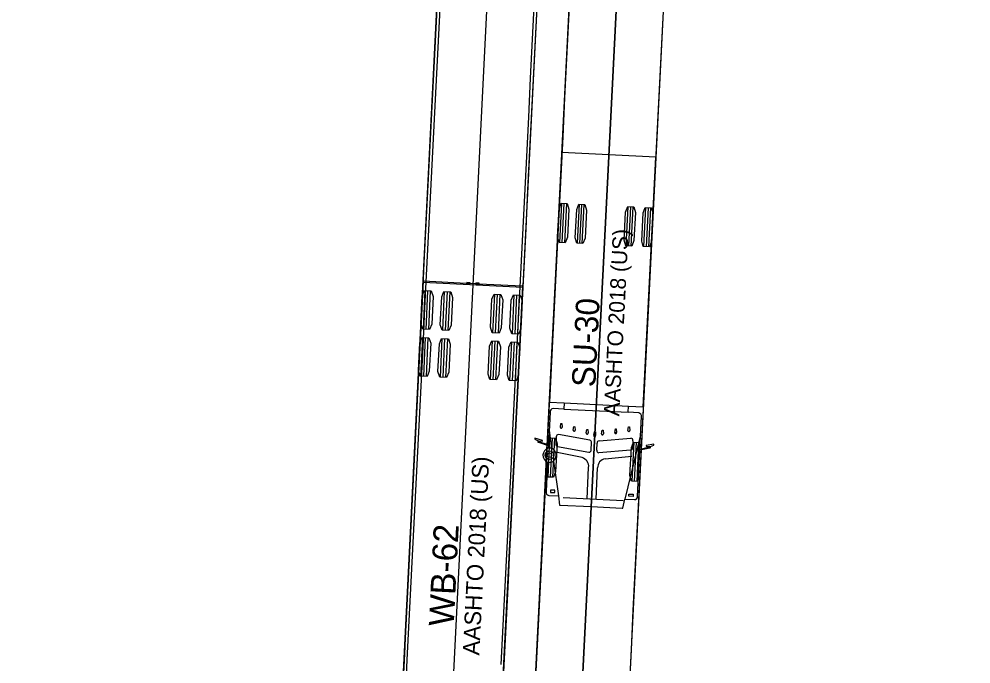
# Model space of a CAD drawing. Extents: x 260275 to 261282, y 610916 to 614143.
# Drawn here: x 260986.2 to 261067.3, y 611872.3 to 611927.2 of the extents above; entities that cross this region are included whole.
import ezdxf

# ---------------------------------------------------------------- set-up
doc = ezdxf.new("R2010")
doc.units = 0
doc.layers.add('GE_X_Alignment', color=7, linetype='Continuous')
doc.layers.add('UT_X_Water_Cells', color=7, linetype='Continuous')

msp = doc.modelspace()

# ---------------------------------------------------------------- linework, layer by layer
at = {"layer": 'GE_X_Alignment'}
msp.add_line((260986.249, 610915.954), (261148.276, 614142.838), dxfattribs=at)
at = {"layer": 'UT_X_Water_Cells'}
for p, q in [((261044.031, 612066.726), (261023.69, 611661.632)), ((261031.95, 612045.486), (261010.925, 611626.741)), ((261032.272, 611908.143), (261032.439, 611911.472)), ((261032.48, 611908.133), (261032.647, 611911.462)), ((261032.688, 611908.122), (261032.855, 611911.452)), ((261033.77, 611908.068), (261033.937, 611911.397)), ((261033.978, 611908.058), (261034.145, 611911.387)), ((261034.186, 611908.047), (261034.353, 611911.376)), ((261037.931, 611907.859), (261038.098, 611911.188)), ((261038.139, 611907.849), (261038.306, 611911.178)), ((261038.347, 611907.838), (261038.515, 611911.167)), ((261039.429, 611907.784), (261039.597, 611911.113)), ((261039.637, 611907.773), (261039.805, 611911.103)), ((261039.846, 611907.763), (261040.013, 611911.092)), ((261020.629, 611904.765), (261029.119, 611904.339)), ((261020.657, 611900.75), (261020.823, 611904.046)), ((261020.886, 611900.739), (261021.052, 611904.035)), ((261021.115, 611900.727), (261021.28, 611904.023)), ((261024.347, 611904.649), (261024.612, 611904.636)), ((261025.137, 611904.61), (261024.614, 611904.636)), ((261024.878, 611904.623), (261024.874, 611904.552)), ((261025.143, 611904.61), (261025.408, 611904.596)), ((261022.305, 611900.667), (261022.471, 611903.963)), ((261022.534, 611900.656), (261022.699, 611903.952)), ((261022.763, 611900.644), (261022.928, 611903.94)), ((261026.583, 611900.453), (261026.749, 611903.749)), ((261026.812, 611900.441), (261026.977, 611903.737)), ((261027.041, 611900.43), (261027.206, 611903.726)), ((261028.231, 611900.37), (261028.396, 611903.666)), ((261028.46, 611900.358), (261028.625, 611903.654)), ((261028.689, 611900.347), (261028.854, 611903.643)), ((261020.457, 611896.755), (261020.622, 611900.051)), ((261020.685, 611896.744), (261020.851, 611900.04)), ((261020.914, 611896.732), (261021.08, 611900.028)), ((261022.105, 611896.672), (261022.27, 611899.968)), ((261022.333, 611896.661), (261022.499, 611899.957)), ((261022.562, 611896.65), (261022.728, 611899.945)), ((261026.382, 611896.458), (261026.548, 611899.754)), ((261026.611, 611896.446), (261026.777, 611899.742)), ((261026.84, 611896.435), (261027.006, 611899.731)), ((261028.03, 611896.375), (261028.196, 611899.671)), ((261028.259, 611896.363), (261028.425, 611899.659)), ((261028.488, 611896.352), (261028.654, 611899.648)), ((261032.633, 611894.488), (261038.118, 611894.213)), ((261032.606, 611893.957), (261038.091, 611893.682)), ((261032.316, 611892.43), (261032.367, 611892.728)), ((261032.367, 611892.728), (261032.449, 611892.724)), ((261032.449, 611892.724), (261032.47, 611892.422)), ((261031.36, 611892.142), (261031.576, 611890.608)), ((261033.421, 611892.164), (261033.472, 611892.462)), ((261033.472, 611892.462), (261033.554, 611892.457)), ((261033.554, 611892.457), (261033.575, 611892.156)), ((261034.527, 611891.926), (261034.578, 611892.223)), ((261034.578, 611892.223), (261034.661, 611892.219)), ((261034.661, 611892.219), (261034.682, 611891.918)), ((261035.166, 611891.725), (261035.217, 611892.023)), ((261035.217, 611892.023), (261035.3, 611892.019)), ((261035.3, 611892.019), (261035.321, 611891.718)), ((261035.822, 611891.861), (261035.873, 611892.158)), ((261035.873, 611892.158), (261035.956, 611892.154)), ((261035.956, 611892.154), (261035.977, 611891.853)), ((261036.947, 611891.973), (261036.998, 611892.285)), ((261036.998, 611892.285), (261037.081, 611892.28)), ((261037.081, 611892.28), (261037.102, 611891.965)), ((261038.074, 611892.141), (261038.125, 611892.439)), ((261038.125, 611892.439), (261038.207, 611892.434)), ((261038.207, 611892.434), (261038.228, 611892.133)), ((261031.269, 611888.168), (261031.436, 611891.498)), ((261031.477, 611888.158), (261031.644, 611891.487)), ((261031.685, 611888.148), (261031.852, 611891.477)), ((261031.968, 611891.592), (261031.937, 611890.976)), ((261034.832, 611891.298), (261032.159, 611891.784)), ((261034.943, 611890.473), (261034.974, 611891.089)), ((261035.418, 611890.449), (261035.449, 611891.065)), ((261035.61, 611891.259), (261038.319, 611891.475)), ((261039.15, 611891.751), (261037.809, 611886.283)), ((261038.426, 611887.809), (261038.594, 611891.138)), ((261038.49, 611891.264), (261038.459, 611890.648)), ((261038.634, 611887.799), (261038.802, 611891.128)), ((261038.843, 611887.788), (261039.01, 611891.117)), ((261034.166, 611889.822), (261031.91, 611890.283)), ((261032.078, 611890.766), (261034.751, 611890.28)), ((261038.298, 611890.454), (261035.589, 611890.238)), ((261031.224, 611889.442), (261031.098, 611886.923)), ((261031.728, 611889.533), (261032.146, 611886.567)), ((261036.126, 611889.724), (261038.404, 611889.955)), ((261034.589, 611886.322), (261034.723, 611888.986)), ((261035.354, 611886.283), (261035.488, 611888.948)), ((261031.48, 611887.057), (261031.471, 611886.863)), ((261031.859, 611887.038), (261031.48, 611887.057)), ((261031.849, 611886.844), (261031.859, 611887.038)), ((261031.471, 611886.863), (261031.849, 611886.844)), ((261032.555, 611886.424), (261037.653, 611886.168)), ((261038.133, 611886.529), (261038.142, 611886.723)), ((261038.511, 611886.51), (261038.133, 611886.529)), ((261038.142, 611886.723), (261038.521, 611886.704)), ((261038.521, 611886.704), (261038.511, 611886.51))]:
    msp.add_line(p, q, dxfattribs=at)
for points in [[(261009.34, 611680.102), (261030.965, 612110.617), (261039.455, 612110.191), (261039.447, 612110.045), (261039.447, 612110.045)], [(261039.447, 612110.045), (261018.12, 611685.301)], [(261020.965, 611687.133), (261041.34, 612092.893), (261049.33, 612092.492), (261049.322, 612092.345), (261049.322, 612092.345)], [(261049.322, 612092.345), (261028.546, 611678.469)], [(261033.183, 611930.456), (261033.016, 611927.127), (261032.849, 611923.799), (261032.682, 611920.47), (261032.515, 611917.141), (261032.348, 611913.813), (261032.181, 611910.484), (261032.014, 611907.155), (261031.846, 611903.827), (261031.679, 611900.498), (261031.512, 611897.17), (261031.345, 611893.841), (261031.178, 611890.512), (261031.011, 611887.184), (261030.844, 611883.855), (261030.676, 611880.526), (261030.509, 611877.198), (261030.342, 611873.869), (261030.175, 611870.541)], [(261033.183, 611930.453), (261033.016, 611927.124), (261032.849, 611923.795), (261032.682, 611920.467), (261032.515, 611917.138), (261032.348, 611913.81), (261032.18, 611910.481), (261032.013, 611907.152), (261031.846, 611903.824), (261031.679, 611900.495), (261031.512, 611897.166), (261031.345, 611893.838), (261031.178, 611890.509), (261031.011, 611887.181), (261030.843, 611883.852), (261030.676, 611880.523), (261030.509, 611877.195), (261030.342, 611873.866), (261030.175, 611870.538)], [(261041.173, 611930.055), (261041.006, 611926.726), (261040.839, 611923.397), (261040.672, 611920.069), (261040.505, 611916.74), (261040.338, 611913.412), (261040.171, 611910.083), (261040.003, 611906.754), (261039.836, 611903.426), (261039.669, 611900.097), (261039.502, 611896.768), (261039.335, 611893.44), (261039.168, 611890.111), (261039.001, 611886.783), (261038.833, 611883.454), (261038.666, 611880.125), (261038.499, 611876.797), (261038.332, 611873.468), (261038.165, 611870.139)], [(261041.173, 611930.051), (261041.006, 611926.723), (261040.839, 611923.394), (261040.672, 611920.066), (261040.505, 611916.737), (261040.338, 611913.408), (261040.17, 611910.08), (261040.003, 611906.751), (261039.836, 611903.423), (261039.669, 611900.094), (261039.502, 611896.765), (261039.335, 611893.437), (261039.168, 611890.108), (261039, 611886.779), (261038.833, 611883.451), (261038.666, 611880.122), (261038.499, 611876.794), (261038.332, 611873.465), (261038.165, 611870.136)], [(261021.882, 611929.704), (261021.714, 611926.376), (261021.547, 611923.047), (261021.38, 611919.718), (261021.213, 611916.39), (261021.046, 611913.061), (261020.879, 611909.732), (261020.712, 611906.404), (261020.544, 611903.075), (261020.377, 611899.746), (261020.21, 611896.418), (261020.043, 611893.089), (261019.876, 611889.76), (261019.709, 611886.432), (261019.542, 611883.103), (261019.374, 611879.774), (261019.207, 611876.446), (261019.04, 611873.117), (261018.873, 611869.789)], [(261022.106, 611929.184), (261021.939, 611925.855), (261021.771, 611922.526), (261021.604, 611919.198), (261021.437, 611915.869), (261021.27, 611912.54), (261021.103, 611909.212), (261020.936, 611905.883), (261020.769, 611902.554), (261020.601, 611899.226), (261020.434, 611895.897), (261020.267, 611892.568), (261020.1, 611889.24), (261019.933, 611885.911), (261019.766, 611882.582), (261019.599, 611879.254), (261019.432, 611875.925), (261019.264, 611872.597), (261019.097, 611869.268)], [(261030.371, 611929.278), (261030.204, 611925.949), (261030.037, 611922.621), (261029.869, 611919.292), (261029.702, 611915.963), (261029.535, 611912.635), (261029.368, 611909.306), (261029.201, 611905.977), (261029.034, 611902.649), (261028.867, 611899.32), (261028.699, 611895.991), (261028.532, 611892.663), (261028.365, 611889.334), (261028.198, 611886.006), (261028.031, 611882.677), (261027.864, 611879.348), (261027.697, 611876.02), (261027.53, 611872.691), (261027.362, 611869.362)], [(261030.096, 611928.782), (261029.929, 611925.454), (261029.761, 611922.125), (261029.594, 611918.796), (261029.427, 611915.468), (261029.26, 611912.139), (261029.093, 611908.81), (261028.926, 611905.482), (261028.759, 611902.153), (261028.591, 611898.825), (261028.424, 611895.496), (261028.257, 611892.167), (261028.09, 611888.839), (261027.923, 611885.51), (261027.756, 611882.181), (261027.589, 611878.853), (261027.421, 611875.524), (261027.254, 611872.195)], [(261038.99, 611893.637), (261038.095, 611893.682), (261038.092, 611893.686), (261038.118, 611894.212), (261038.129, 611894.212), (261039.371, 611894.15), (261040.438, 611915.41), (261036.443, 611915.61), (261032.448, 611915.811), (261031.381, 611894.551), (261032.622, 611894.489), (261032.633, 611894.487), (261032.607, 611893.961), (261032.603, 611893.957), (261031.708, 611894.002)], [(261020.655, 611904.835), (261020.633, 611904.836), (261018.229, 611856.967), (261022.474, 611856.754), (261026.719, 611856.541), (261029.122, 611904.41), (261029.1, 611904.411)], [(261024.618, 611904.706), (261024.352, 611904.72), (261024.35, 611904.719), (261024.347, 611904.65), (261024.311, 611904.651), (261020.68, 611904.834), (261020.679, 611904.834)], [(261029.076, 611904.412), (261029.075, 611904.412), (261025.444, 611904.594), (261025.408, 611904.596), (261025.412, 611904.666), (261025.41, 611904.667), (261025.144, 611904.68)], [(261031.438, 611893.7), (261031.299, 611890.929), (261031.294, 611890.918), (261030.488, 611891.178), (261030.488, 611891.178)], [(261039.921, 611890.704), (261039.92, 611890.704), (261039.093, 611890.526), (261039.089, 611890.538), (261039.228, 611893.309)], [(261030.478, 611891.199), (261030.48, 611891.243), (261030.48, 611891.243), (261030.797, 611891.236), (261030.8, 611891.236), (261030.803, 611891.292), (261030.8, 611891.293), (261030.152, 611891.465), (261030.149, 611891.465), (261030.146, 611891.4), (261030.434, 611891.254), (261030.434, 611891.254), (261030.432, 611891.206)], [(261030.469, 611891.132), (261030.47, 611891.131), (261031.289, 611890.864), (261031.295, 611890.851), (261031.284, 611890.624)], [(261038.888, 611886.532), (261039.085, 611890.46), (261039.092, 611890.472), (261039.934, 611890.656), (261039.935, 611890.656)], [(261039.979, 611890.727), (261039.982, 611890.774), (261039.983, 611890.775), (261040.284, 611890.891), (261040.287, 611890.956), (261040.284, 611890.956), (261039.622, 611890.85), (261039.619, 611890.849), (261039.616, 611890.793), (261039.619, 611890.793), (261039.935, 611890.769), (261039.936, 611890.768), (261039.933, 611890.724)], [(261031.336, 611886.608), (261032.142, 611886.567), (261032.147, 611886.563), (261032.256, 611885.785), (261032.298, 611885.781), (261034.939, 611885.648), (261037.579, 611885.515), (261037.621, 611885.515), (261037.808, 611886.278), (261037.813, 611886.283), (261038.62, 611886.242)]]:
    msp.add_lwpolyline(points, dxfattribs=at)
for points in [[(261032.739, 611908.12), (261032.22, 611908.146), (261032.087, 611908.62), (261032.207, 611911.017), (261032.387, 611911.475), (261032.907, 611911.449), (261033.04, 611910.975), (261032.919, 611908.578)], [(261034.238, 611908.045), (261033.718, 611908.071), (261033.585, 611908.545), (261033.706, 611910.942), (261033.885, 611911.4), (261034.405, 611911.374), (261034.538, 611910.9), (261034.417, 611908.503)], [(261038.399, 611907.836), (261037.88, 611907.862), (261037.747, 611908.336), (261037.867, 611910.733), (261038.047, 611911.191), (261038.566, 611911.165), (261038.699, 611910.691), (261038.579, 611908.294)], [(261039.897, 611907.76), (261039.378, 611907.787), (261039.245, 611908.26), (261039.365, 611910.657), (261039.545, 611911.116), (261040.064, 611911.09), (261040.197, 611910.616), (261040.077, 611908.219)], [(261021.172, 611900.724), (261020.6, 611900.753), (261020.451, 611901.223), (261020.571, 611903.596), (261020.766, 611904.049), (261021.337, 611904.02), (261021.486, 611903.55), (261021.367, 611901.177)], [(261022.82, 611900.642), (261022.248, 611900.67), (261022.099, 611901.14), (261022.219, 611903.513), (261022.414, 611903.966), (261022.985, 611903.937), (261023.134, 611903.467), (261023.015, 611901.094)], [(261027.098, 611900.427), (261026.526, 611900.456), (261026.377, 611900.926), (261026.496, 611903.299), (261026.692, 611903.751), (261027.263, 611903.723), (261027.412, 611903.253), (261027.293, 611900.88)], [(261028.745, 611900.344), (261028.174, 611900.373), (261028.025, 611900.843), (261028.144, 611903.216), (261028.34, 611903.669), (261028.911, 611903.64), (261029.06, 611903.17), (261028.941, 611900.797)], [(261020.971, 611896.729), (261020.4, 611896.758), (261020.251, 611897.228), (261020.37, 611899.601), (261020.565, 611900.054), (261021.137, 611900.025), (261021.286, 611899.555), (261021.166, 611897.182)], [(261022.619, 611896.647), (261022.048, 611896.675), (261021.899, 611897.145), (261022.018, 611899.518), (261022.213, 611899.971), (261022.785, 611899.943), (261022.933, 611899.472), (261022.814, 611897.099)], [(261026.897, 611896.432), (261026.326, 611896.461), (261026.177, 611896.931), (261026.296, 611899.304), (261026.491, 611899.756), (261027.062, 611899.728), (261027.211, 611899.258), (261027.092, 611896.885)], [(261028.545, 611896.349), (261027.974, 611896.378), (261027.825, 611896.848), (261027.944, 611899.221), (261028.139, 611899.674), (261028.71, 611899.645), (261028.859, 611899.175), (261028.74, 611896.802)], [(261031.736, 611888.145), (261031.217, 611888.171), (261031.084, 611888.645), (261031.204, 611891.042), (261031.384, 611891.5), (261031.904, 611891.474), (261032.037, 611891), (261031.916, 611888.603)], [(261038.894, 611887.786), (261038.375, 611887.812), (261038.242, 611888.286), (261038.362, 611890.683), (261038.542, 611891.141), (261039.061, 611891.115), (261039.194, 611890.641), (261039.074, 611888.244)]]:
    msp.add_lwpolyline(points, close=True, dxfattribs=at)
for centre, radius in [((261020.669, 611904.868), 0.0266), ((261029.09, 611904.446), 0.0266), ((261031.399, 611890.026), 0.374), ((261031.399, 611890.026), 0.193)]:
    msp.add_circle(centre, radius, dxfattribs=at)
for centre, radius, start, end in [((261020.669, 611904.869), 0.0363, 286.88607, 248.0487), ((261024.616, 611904.671), 0.0354, 91.41704, 263.6025), ((261024.616, 611904.671), 0.0352, 266.52344, 87.10992), ((261025.142, 611904.645), 0.0352, 87.14108, 267.72757), ((261025.143, 611904.645), 0.0352, 266.91304, 89.55244), ((261029.09, 611904.446), 0.0363, 286.20231, 247.36494), ((261031.76, 611893.684), 0.323, 99.2771, 177.1255), ((261038.906, 611893.325), 0.323, 357.1255, 74.97391), ((261032.404, 611892.407), 0.091, 165.44206, 259.60593), ((261032.38, 611892.408), 0.0909, 274.60942, 8.84462), ((261033.509, 611892.141), 0.091, 165.44206, 259.60593), ((261033.485, 611892.142), 0.0909, 274.60942, 8.84462), ((261034.616, 611891.903), 0.091, 165.44206, 259.60593), ((261034.592, 611891.904), 0.0909, 274.60942, 8.84462), ((261035.91, 611891.838), 0.0909, 165.40639, 259.64159), ((261035.887, 611891.839), 0.091, 274.64508, 8.80895), ((261037.035, 611891.964), 0.0909, 165.40639, 259.64159), ((261037.012, 611891.965), 0.091, 274.64508, 8.80895), ((261038.162, 611892.118), 0.0909, 165.40639, 259.64159), ((261038.138, 611892.119), 0.091, 274.64508, 8.80895), ((261030.451, 611891.169), 0.0418, 117.61865, 294.63358), ((261030.445, 611891.17), 0.0434, 11.03902, 41.7118), ((261032.152, 611891.6), 0.184, 87.71808, 182.58934), ((261034.783, 611891.112), 0.193, 353.06366, 74.98801), ((261035.255, 611891.702), 0.091, 165.44206, 259.60593), ((261035.231, 611891.704), 0.091, 274.64508, 8.80895), ((261035.641, 611891.069), 0.193, 99.26299, 181.18734), ((261038.308, 611891.291), 0.184, 351.66167, 86.53293), ((261031.466, 611890.022), 0.628, 106.8788, 247.3705), ((261031.403, 611890.113), 0.524, 49.38452, 103.18459), ((261031.33, 611890.036), 0.63, 356.4803, 48.88311), ((261032.128, 611890.952), 0.193, 173.06859, 254.98308), ((261034.759, 611890.464), 0.184, 267.72364, 2.58377), ((261035.6, 611890.422), 0.184, 171.66723, 266.52737), ((261038.267, 611890.644), 0.193, 279.26792, 1.18241), ((261039.962, 611890.692), 0.0434, 132.53921, 163.21198), ((261039.956, 611890.692), 0.0418, 239.61742, 56.63235), ((261031.395, 611889.94), 0.526, 251.07067, 309.31667), ((261031.33, 611890.021), 0.629, 309.17109, 357.86038), ((261033.956, 611889.079), 0.773, 353.15088, 74.23504), ((261036.26, 611888.963), 0.773, 100.01597, 181.10013), ((261031.377, 611886.887), 0.282, 172.49767, 261.5771), ((261038.606, 611886.524), 0.282, 272.67391, 1.75333)]:
    msp.add_arc(centre, radius, start, end, dxfattribs=at)

# ---------------------------------------------------------------- texts
for s, height, p in [('AASHTO 2018 (US)', 1.33333, (261037.333, 611893.323)), ('SU-30', 2, (261035.287, 611895.786)), ('AASHTO 2018 (US)', 1.41667, (261025.423, 611872.961)), ('WB-62', 2.125, (261023.241, 611875.426))]:
    msp.add_text(s, height=height, rotation=87.1255, dxfattribs=at).set_placement(p)

doc.saveas('drawing.dxf')
